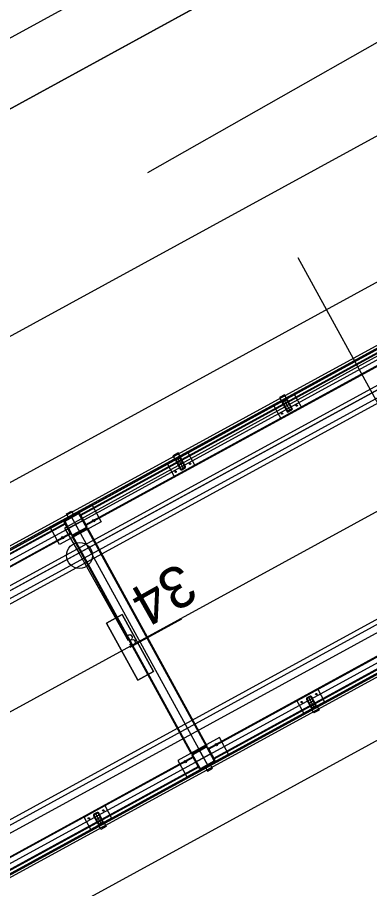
# Model space of a CAD drawing. Extents: x -783978 to -783565, y -1064821 to -1064596.
# Drawn here: x -783750.16 to -783747.19, y -1064675.51 to -1064668.14 of the extents above; entities that cross this region are included whole.
import ezdxf

# ---------------------------------------------------------------- set-up
doc = ezdxf.new("R2010")
doc.units = 0
for name, color, linetype in [('Default', 7, 'Continuous'), ('PS 01_01_10', 7, 'Continuous'), ('PS 01_02_501', 7, 'Continuous'), ('PS 01_02_502', 7, 'Continuous'), ('SO 01_11_01', 7, 'Continuous'), ('SO 01_20_01', 7, 'Continuous'), ('SO 01_50_01', 7, 'Continuous'), ('SO 01_74_01', 7, 'Continuous'), ('SO 01_86_03', 7, 'Continuous'), ('SO 01_86_04', 7, 'Continuous')]:
    doc.layers.add(name, color=color, linetype=linetype)

# ---------------------------------------------------------------- blocks, each defined once
blk = doc.blocks.new('POINT_DISPLAY')
at = {"layer": 'Default'}
blk.add_line((0, 0), (0, 0), dxfattribs=at)

msp = doc.modelspace()

# ---------------------------------------------------------------- linework, layer by layer
at = {"layer": 'PS 01_01_10'}
msp.add_lwpolyline([(-783718.9415, -1064658.9356), (-783725.9639, -1064662.6889), (-783732.3538, -1064665.9121), (-783735.2095, -1064660.6967), (-783789.362, -1064690.3481), (-783783.8255, -1064700.4409), (-783871.4362, -1064748.4249), (-783875.857, -1064749.8347)], dxfattribs=at)
at = {"layer": 'PS 01_02_501'}
msp.add_lwpolyline([(-783952.3105, -1064789.972), (-783925.027, -1064771.233), (-783922.857, -1064767.935), (-783921.1315, -1064767.225), (-783922.344, -1064769.056), (-783920.816, -1064771.043), (-783917.67, -1064770.417), (-783911.05, -1064766.471), (-783887.429, -1064753.525), (-783871.4362, -1064748.4249), (-783783.8277, -1064700.4386), (-783789.362, -1064690.3481), (-783735.2263, -1064660.7067), (-783727.1901, -1064659.072), (-783724.297, -1064658.4835), (-783715.521, -1064653.988), (-783697.391, -1064644.148), (-783676.268, -1064633.506), (-783655.138, -1064621.894)], dxfattribs=at)
at = {"layer": 'PS 01_02_502'}
msp.add_lwpolyline([(-783952.3105, -1064789.972), (-783925.027, -1064771.233), (-783922.857, -1064767.935), (-783921.1315, -1064767.225), (-783922.344, -1064769.056), (-783920.816, -1064771.043), (-783917.67, -1064770.417), (-783911.05, -1064766.471), (-783887.429, -1064753.525), (-783871.4362, -1064748.4249), (-783783.8277, -1064700.4386), (-783789.362, -1064690.3481), (-783735.2263, -1064660.7067), (-783727.1901, -1064659.072), (-783724.297, -1064658.4835), (-783715.521, -1064653.988), (-783697.391, -1064644.148), (-783676.268, -1064633.506), (-783655.138, -1064621.894)], dxfattribs=at)
at = {"layer": 'SO 01_11_01'}
for p, q in [((-783772.8819, -1064683.2217), (-783730.898, -1064660.279)), ((-783749.059, -1064669.4549), (-783743.8421, -1064666.4911))]:
    msp.add_line(p, q, dxfattribs=at)
at = {"layer": 'SO 01_20_01'}
for p, q in [((-783735.0054, -1064663.7532), (-783787.4671, -1064692.4555)), ((-783735.2041, -1064664.4318), (-783786.7885, -1064692.6541)), ((-783786.6445, -1064692.9173), (-783735.3233, -1064664.839)), ((-783738.0171, -1064666.3812), (-783786.4402, -1064692.874)), ((-783786.421, -1064692.9091), (-783737.9979, -1064666.4163)), ((-783737.8741, -1064667.2605), (-783785.3352, -1064693.2269)), ((-783785.6531, -1064694.3127), (-783737.23, -1064667.82)), ((-783737.2108, -1064667.855), (-783785.6339, -1064694.3478)), ((-783737.0912, -1064667.858), (-783785.7805, -1064694.4964)), ((-783785.6366, -1064694.7596), (-783736.9472, -1064668.1212)), ((-783746.2961, -1064673.8055), (-783785.8354, -1064695.4379))]:
    msp.add_line(p, q, dxfattribs=at)
at = {"layer": 'SO 01_50_01'}
for p, q in [((-783786.7885, -1064692.6541), (-783725.4827, -1064659.1131)), ((-783753.521, -1064670.1216), (-783749.1346, -1064667.7218)), ((-783753.521, -1064670.1216), (-783749.1346, -1064667.7218)), ((-783753.521, -1064670.1216), (-783749.1346, -1064667.7218)), ((-783753.521, -1064670.1216), (-783749.1346, -1064667.7218)), ((-783747.3107, -1064671.0555), (-783742.9243, -1064668.6556)), ((-783747.3106, -1064671.0555), (-783742.9242, -1064668.6557)), ((-783747.3106, -1064671.0555), (-783742.9242, -1064668.6557)), ((-783746.8307, -1064671.9327), (-783747.7907, -1064670.1782)), ((-783751.6971, -1064673.4553), (-783747.3107, -1064671.0555)), ((-783751.6971, -1064673.4554), (-783747.3106, -1064671.0555)), ((-783751.6971, -1064673.4554), (-783747.3106, -1064671.0555))]:
    msp.add_line(p, q, dxfattribs=at)
at = {"layer": 'SO 01_74_01'}
for p, q in [((-783735.2185, -1064664.4055), (-783786.6099, -1064692.5222)), ((-783786.6003, -1064692.5398), (-783735.2089, -1064664.423)), ((-783747.0618, -1064670.9478), (-783749.6278, -1064672.3517)), ((-783747.0587, -1064670.9533), (-783749.6248, -1064672.3572)), ((-783749.5828, -1064672.4339), (-783747.0168, -1064671.03)), ((-783749.5798, -1064672.4394), (-783747.0138, -1064671.0355)), ((-783747.9044, -1064671.3347), (-783747.9483, -1064671.3587)), ((-783747.9483, -1064671.3587), (-783747.9291, -1064671.3938)), ((-783747.8996, -1064671.3435), (-783747.9435, -1064671.3675)), ((-783747.9435, -1064671.3675), (-783747.9339, -1064671.385)), ((-783747.9339, -1064671.385), (-783747.89, -1064671.361)), ((-783747.9291, -1064671.3938), (-783747.8852, -1064671.3698)), ((-783747.8852, -1064671.3698), (-783747.9044, -1064671.3347)), ((-783747.89, -1064671.361), (-783747.8996, -1064671.3435)), ((-783748.8037, -1064671.8267), (-783748.8475, -1064671.8507)), ((-783748.7845, -1064671.8618), (-783748.8037, -1064671.8267)), ((-783748.8475, -1064671.8507), (-783748.8283, -1064671.8858)), ((-783748.7989, -1064671.8355), (-783748.8427, -1064671.8594)), ((-783748.8427, -1064671.8594), (-783748.8331, -1064671.877)), ((-783748.8331, -1064671.877), (-783748.7893, -1064671.853)), ((-783748.8283, -1064671.8858), (-783748.7845, -1064671.8618)), ((-783748.7893, -1064671.853), (-783748.7989, -1064671.8355)), ((-783749.7467, -1064672.3426), (-783749.7029, -1064672.3186)), ((-783749.7275, -1064672.3777), (-783749.7467, -1064672.3426)), ((-783749.7029, -1064672.3186), (-783749.6837, -1064672.3537)), ((-783749.6837, -1064672.3537), (-783749.7275, -1064672.3777)), ((-783749.6278, -1064672.3517), (-783749.5798, -1064672.4394)), ((-783749.6248, -1064672.3572), (-783749.5828, -1064672.4339)), ((-783749.7594, -1064672.4237), (-783752.3255, -1064673.8276)), ((-783749.7564, -1064672.4292), (-783752.3224, -1064673.8331)), ((-783749.7114, -1064672.5114), (-783749.7594, -1064672.4237)), ((-783749.7144, -1064672.5059), (-783749.7564, -1064672.4292)), ((-783749.6994, -1064672.5333), (-783749.5678, -1064672.4613)), ((-783749.6924, -1064672.5295), (-783749.5748, -1064672.4652)), ((-783749.5748, -1064672.4652), (-783748.5669, -1064674.3075)), ((-783749.5678, -1064672.4613), (-783748.5599, -1064674.3036)), ((-783752.2805, -1064673.9098), (-783749.7144, -1064672.5059)), ((-783752.2775, -1064673.9153), (-783749.7114, -1064672.5114)), ((-783748.6915, -1064674.3756), (-783749.6994, -1064672.5333)), ((-783748.6845, -1064674.3718), (-783749.6924, -1064672.5295)), ((-783745.9818, -1064672.9216), (-783748.5479, -1064674.3256)), ((-783745.9788, -1064672.9272), (-783748.5449, -1064674.3311)), ((-783785.4388, -1064694.6628), (-783745.8293, -1064672.9921)), ((-783745.8197, -1064673.0096), (-783785.4292, -1064694.6803)), ((-783748.5029, -1064674.4078), (-783745.9368, -1064673.0038)), ((-783748.4999, -1064674.4133), (-783745.9338, -1064673.0094)), ((-783747.6764, -1064673.9913), (-783747.6325, -1064673.9673)), ((-783747.6325, -1064673.9673), (-783747.6133, -1064674.0023)), ((-783747.6572, -1064674.0263), (-783747.6764, -1064673.9913)), ((-783747.6716, -1064674), (-783747.6277, -1064673.976)), ((-783747.662, -1064674.0176), (-783747.6716, -1064674)), ((-783747.6181, -1064673.9936), (-783747.662, -1064674.0176)), ((-783747.6133, -1064674.0023), (-783747.6572, -1064674.0263)), ((-783747.6277, -1064673.976), (-783747.6181, -1064673.9936)), ((-783748.5599, -1064674.3036), (-783748.6915, -1064674.3756)), ((-783748.5669, -1064674.3075), (-783748.6845, -1064674.3718)), ((-783748.5479, -1064674.3256), (-783748.4999, -1064674.4133)), ((-783748.5449, -1064674.3311), (-783748.5029, -1064674.4078)), ((-783748.6795, -1064674.3976), (-783751.2455, -1064675.8015)), ((-783748.6764, -1064674.4031), (-783751.2425, -1064675.807)), ((-783748.6315, -1064674.4853), (-783748.6795, -1064674.3976)), ((-783748.6345, -1064674.4798), (-783748.6764, -1064674.4031)), ((-783751.2006, -1064675.8837), (-783748.6345, -1064674.4798)), ((-783751.1975, -1064675.8892), (-783748.6315, -1064674.4853)), ((-783748.5317, -1064674.4592), (-783748.5756, -1064674.4832)), ((-783748.5756, -1064674.4832), (-783748.5564, -1064674.5183)), ((-783748.5125, -1064674.4943), (-783748.5317, -1064674.4592)), ((-783748.5564, -1064674.5183), (-783748.5125, -1064674.4943)), ((-783749.4748, -1064674.9752), (-783749.431, -1064674.9512)), ((-783749.4556, -1064675.0103), (-783749.4748, -1064674.9752)), ((-783749.47, -1064674.984), (-783749.4262, -1064674.96)), ((-783749.4604, -1064675.0015), (-783749.47, -1064674.984)), ((-783749.4166, -1064674.9775), (-783749.4604, -1064675.0015)), ((-783749.4118, -1064674.9863), (-783749.4556, -1064675.0103)), ((-783749.431, -1064674.9512), (-783749.4118, -1064674.9863)), ((-783749.4262, -1064674.96), (-783749.4166, -1064674.9775))]:
    msp.add_line(p, q, dxfattribs=at)
for points in [[(-783735.1681, -1064664.4976), (-783787.4762, -1064693.1159)], [(-783734.0882, -1064666.4715), (-783786.3963, -1064695.0898)], [(-783747.8935, -1064671.3743), (-783747.9208, -1064671.3893)], [(-783747.8905, -1064671.3799), (-783747.9178, -1064671.3948)], [(-783747.9072, -1064671.3818), (-783747.8592, -1064671.4695)], [(-783747.8473, -1064671.4523), (-783747.8862, -1064671.3811)], [(-783747.8418, -1064671.4492), (-783747.8807, -1064671.3781)], [(-783747.9246, -1064671.4021), (-783747.8856, -1064671.4732)], [(-783747.919, -1064671.3991), (-783747.8801, -1064671.4702)], [(-783747.8612, -1064671.4137), (-783747.9051, -1064671.4377)], [(-783747.8758, -1064671.4715), (-783747.8486, -1064671.4565)], [(-783747.8728, -1064671.477), (-783747.8455, -1064671.4621)], [(-783748.8238, -1064671.8941), (-783748.7849, -1064671.9652)], [(-783748.7928, -1064671.8663), (-783748.82, -1064671.8812)], [(-783748.8183, -1064671.891), (-783748.7793, -1064671.9622)], [(-783748.7897, -1064671.8718), (-783748.817, -1064671.8868)], [(-783748.8064, -1064671.8738), (-783748.7584, -1064671.9615)], [(-783748.7605, -1064671.9056), (-783748.8043, -1064671.9296)], [(-783748.7465, -1064671.9442), (-783748.7855, -1064671.8731)], [(-783748.741, -1064671.9412), (-783748.7799, -1064671.8701)], [(-783748.7751, -1064671.9634), (-783748.7478, -1064671.9485)], [(-783748.772, -1064671.969), (-783748.7448, -1064671.954)], [(-783749.7609, -1064672.396), (-783749.6503, -1064672.3355)], [(-783749.757, -1064672.403), (-783749.6465, -1064672.3425)], [(-783749.6411, -1064672.3441), (-783749.5806, -1064672.4546)], [(-783749.6341, -1064672.3403), (-783749.5736, -1064672.4508)], [(-783749.7052, -1064672.5228), (-783749.7656, -1064672.4123)], [(-783749.6982, -1064672.519), (-783749.7586, -1064672.4084)], [(-783749.6038, -1064672.3955), (-783749.7354, -1064672.4675)], [(-783749.7056, -1064672.3657), (-783748.5537, -1064674.4712)], [(-783749.7056, -1064672.3657), (-783749.6336, -1064672.4973)], [(-783749.5822, -1064672.4601), (-783749.6927, -1064672.5206)], [(-783749.5783, -1064672.4671), (-783749.6889, -1064672.5276)], [(-783747.6888, -1064673.8841), (-783747.7161, -1064673.899)], [(-783747.6858, -1064673.8896), (-783747.7131, -1064673.9045)], [(-783747.7025, -1064673.8915), (-783747.6545, -1064673.9793)], [(-783747.6426, -1064673.962), (-783747.6815, -1064673.8908)], [(-783747.6371, -1064673.959), (-783747.676, -1064673.8878)], [(-783747.7199, -1064673.9118), (-783747.6809, -1064673.983)], [(-783747.7143, -1064673.9088), (-783747.6754, -1064673.9799)], [(-783747.6565, -1064673.9234), (-783747.7004, -1064673.9474)], [(-783747.6711, -1064673.9812), (-783747.6438, -1064673.9663)], [(-783747.6681, -1064673.9867), (-783747.6408, -1064673.9718)], [(-783748.6809, -1064674.3699), (-783748.5704, -1064674.3094)], [(-783748.6771, -1064674.3769), (-783748.5666, -1064674.3164)], [(-783748.5611, -1064674.318), (-783748.5007, -1064674.4285)], [(-783748.5541, -1064674.3142), (-783748.4936, -1064674.4247)], [(-783748.6252, -1064674.4967), (-783748.6857, -1064674.3862)], [(-783748.6182, -1064674.4929), (-783748.6787, -1064674.3823)], [(-783748.5239, -1064674.3694), (-783748.6555, -1064674.4414)], [(-783748.6257, -1064674.3396), (-783748.5537, -1064674.4712)], [(-783748.5022, -1064674.434), (-783748.6128, -1064674.4944)], [(-783748.4984, -1064674.441), (-783748.6089, -1064674.5015)], [(-783749.5183, -1064674.8958), (-783749.4794, -1064674.9669)], [(-783749.4873, -1064674.868), (-783749.5145, -1064674.8829)], [(-783749.5128, -1064674.8927), (-783749.4738, -1064674.9639)], [(-783749.4842, -1064674.8735), (-783749.5115, -1064674.8885)], [(-783749.5009, -1064674.8755), (-783749.4529, -1064674.9632)], [(-783749.455, -1064674.9073), (-783749.4988, -1064674.9313)], [(-783749.441, -1064674.9459), (-783749.48, -1064674.8748)], [(-783749.4355, -1064674.9429), (-783749.4744, -1064674.8718)], [(-783749.4696, -1064674.9651), (-783749.4423, -1064674.9502)], [(-783749.4665, -1064674.9707), (-783749.4393, -1064674.9557)]]:
    msp.add_lwpolyline(points, dxfattribs=at)
for points in [[(-783747.8194, -1064671.3338), (-783747.9949, -1064671.4298), (-783747.9373, -1064671.5351), (-783747.7619, -1064671.4391)], [(-783747.8852, -1064671.3698), (-783747.9291, -1064671.3938), (-783747.8811, -1064671.4815), (-783747.8372, -1064671.4575)], [(-783748.7187, -1064671.8258), (-783748.8941, -1064671.9218), (-783748.8365, -1064672.027), (-783748.6611, -1064671.931)], [(-783749.4534, -1064672.4101), (-783749.8043, -1064672.6021), (-783749.8811, -1064672.4617), (-783749.5302, -1064672.2697)], [(-783747.5667, -1064673.9313), (-783747.7422, -1064674.0272), (-783747.7998, -1064673.922), (-783747.6243, -1064673.826)], [(-783748.455, -1064674.2349), (-783748.8059, -1064674.4268), (-783748.7291, -1064674.5672), (-783748.3782, -1064674.3752)], [(-783749.3652, -1064674.9152), (-783749.5406, -1064675.0112), (-783749.5982, -1064674.9059), (-783749.4228, -1064674.8099)]]:
    msp.add_lwpolyline(points, close=True, dxfattribs=at)
for centre, radius in [((-783747.8026, -1064671.4272), 0.006), ((-783747.9254, -1064671.4944), 0.006), ((-783748.8246, -1064671.9863), 0.006), ((-783748.7018, -1064671.9191), 0.006), ((-783749.5164, -1064672.399), 0.01), ((-783749.7796, -1064672.543), 0.01), ((-783747.6362, -1064673.8667), 0.006), ((-783747.7591, -1064673.9339), 0.006), ((-783748.4797, -1064674.294), 0.01), ((-783748.7429, -1064674.4379), 0.01), ((-783749.4347, -1064674.8506), 0.006), ((-783749.5575, -1064674.9178), 0.006)]:
    msp.add_circle(centre, radius, dxfattribs=at)
for centre, radius, start, end in [((-783747.9163, -1064671.3976), 0.00945, 118.68349, 208.68349), ((-783747.889, -1064671.3826), 0.00945, 28.68349, 118.68349), ((-783747.889, -1064671.3826), 0.00315, 28.68349, 118.68349), ((-783747.9163, -1064671.3976), 0.00315, 118.68349, 208.68349), ((-783747.8501, -1064671.4538), 0.00315, 298.68349, 28.68349), ((-783747.8501, -1064671.4538), 0.00945, 298.68349, 28.68349), ((-783747.8774, -1064671.4687), 0.00945, 208.68349, 298.68349), ((-783747.8774, -1064671.4687), 0.00315, 208.68349, 298.68349), ((-783748.8155, -1064671.8895), 0.00945, 118.68349, 208.68349), ((-783748.8155, -1064671.8895), 0.00315, 118.68349, 208.68349), ((-783748.7882, -1064671.8746), 0.00945, 28.68349, 118.68349), ((-783748.7882, -1064671.8746), 0.00315, 28.68349, 118.68349), ((-783748.7766, -1064671.9607), 0.00945, 208.68349, 298.68349), ((-783748.7766, -1064671.9607), 0.00315, 208.68349, 298.68349), ((-783748.7493, -1064671.9457), 0.00315, 298.68349, 28.68349), ((-783748.7493, -1064671.9457), 0.00945, 298.68349, 28.68349), ((-783749.6446, -1064672.346), 0.012, 28.68349, 118.68349), ((-783749.6446, -1064672.346), 0.004, 28.68349, 118.68349), ((-783749.7551, -1064672.4065), 0.012, 118.68349, 208.68349), ((-783749.7551, -1064672.4065), 0.004, 118.68349, 208.68349), ((-783749.5841, -1064672.4566), 0.004, 298.68349, 28.68349), ((-783749.5841, -1064672.4566), 0.012, 298.68349, 28.68349), ((-783749.6946, -1064672.517), 0.012, 208.68349, 298.68349), ((-783749.6946, -1064672.517), 0.004, 208.68349, 298.68349), ((-783747.6843, -1064673.8923), 0.00945, 28.68349, 118.68349), ((-783747.6843, -1064673.8923), 0.00315, 28.68349, 118.68349), ((-783747.7116, -1064673.9073), 0.00945, 118.68349, 208.68349), ((-783747.7116, -1064673.9073), 0.00315, 118.68349, 208.68349), ((-783747.6454, -1064673.9635), 0.00315, 298.68349, 28.68349), ((-783747.6454, -1064673.9635), 0.00945, 298.68349, 28.68349), ((-783747.6726, -1064673.9784), 0.00945, 208.68349, 298.68349), ((-783747.6726, -1064673.9784), 0.00315, 208.68349, 298.68349), ((-783748.5646, -1064674.3199), 0.012, 28.68349, 118.68349), ((-783748.5646, -1064674.3199), 0.004, 28.68349, 118.68349), ((-783748.6752, -1064674.3804), 0.012, 118.68349, 208.68349), ((-783748.6752, -1064674.3804), 0.004, 118.68349, 208.68349), ((-783748.5042, -1064674.4305), 0.004, 298.68349, 28.68349), ((-783748.5042, -1064674.4305), 0.012, 298.68349, 28.68349), ((-783748.6147, -1064674.4909), 0.012, 208.68349, 298.68349), ((-783748.6147, -1064674.4909), 0.004, 208.68349, 298.68349), ((-783749.51, -1064674.8912), 0.00945, 118.68349, 208.68349), ((-783749.51, -1064674.8912), 0.00315, 118.68349, 208.68349), ((-783749.4827, -1064674.8763), 0.00945, 28.68349, 118.68349), ((-783749.4827, -1064674.8763), 0.00315, 28.68349, 118.68349), ((-783749.4711, -1064674.9624), 0.00945, 208.68349, 298.68349), ((-783749.4711, -1064674.9624), 0.00315, 208.68349, 298.68349), ((-783749.4438, -1064674.9474), 0.00315, 298.68349, 28.68349), ((-783749.4438, -1064674.9474), 0.00945, 298.68349, 28.68349)]:
    msp.add_arc(centre, radius, start, end, dxfattribs=at)
at = {"layer": 'SO 01_86_03'}
for points in [[(-783722.5212, -1064661.7932), (-783724.8208, -1064663.0486), (-783735.2095, -1064660.6967), (-783787.333, -1064689.2371), (-783786.8168, -1064690.1799), (-783783.3595, -1064696.8031), (-783781.9388, -1064699.4088), (-783783.8277, -1064700.4386), (-783871.4362, -1064748.4249), (-783875.857, -1064749.8347), (-783877.5381, -1064747.3925), (-783875.857, -1064749.8347), (-783887.429, -1064753.525), (-783911.05, -1064766.471), (-783917.67, -1064770.417), (-783920.816, -1064771.043), (-783922.344, -1064769.056), (-783922.498, -1064767.051)], [(-783747.0305, -1064676.621), (-783747.6236, -1064677.108), (-783750.7299, -1064678.7824), (-783751.6662, -1064678.8522), (-783782.6812, -1064695.8307), (-783782.8877, -1064696.6917), (-783783.0615, -1064696.8198), (-783783.3595, -1064696.8031), (-783786.8168, -1064690.1799), (-783787.333, -1064689.2371), (-783735.2095, -1064660.6967), (-783724.8208, -1064663.0486), (-783722.5212, -1064661.7932)]]:
    msp.add_lwpolyline(points, dxfattribs=at)
at = {"layer": 'SO 01_86_04'}
for p, q in [((-783749.643, -1064672.6735), (-783749.2252, -1064673.4133)), ((-783749.276, -1064673.1937), (-783749.4076, -1064673.2657)), ((-783749.276, -1064673.1937), (-783749.4076, -1064673.2657)), ((-783749.4076, -1064673.2657), (-783749.276, -1064673.1937)), ((-783749.4076, -1064673.2657), (-783749.276, -1064673.1937)), ((-783749.012, -1064673.6762), (-783749.276, -1064673.1937)), ((-783749.012, -1064673.6762), (-783749.276, -1064673.1937)), ((-783749.276, -1064673.1937), (-783749.012, -1064673.6762)), ((-783749.276, -1064673.1937), (-783749.012, -1064673.6762)), ((-783749.2098, -1064673.471), (-783748.7711, -1064673.231)), ((-783749.4076, -1064673.2657), (-783749.1436, -1064673.7482)), ((-783749.4076, -1064673.2657), (-783749.1436, -1064673.7482)), ((-783749.1436, -1064673.7482), (-783749.4076, -1064673.2657)), ((-783749.1436, -1064673.7482), (-783749.4076, -1064673.2657)), ((-783749.1436, -1064673.7482), (-783749.012, -1064673.6762)), ((-783749.1436, -1064673.7482), (-783749.012, -1064673.6762)), ((-783749.012, -1064673.6762), (-783749.1436, -1064673.7482)), ((-783749.012, -1064673.6762), (-783749.1436, -1064673.7482))]:
    msp.add_line(p, q, dxfattribs=at)
for points in [[(-783735.4626, -1064664.5844), (-783749.7616, -1064672.4637), (-783749.643, -1064672.6735)], [(-783738.3222, -1064666.4797), (-783740.5325, -1064667.689), (-783743.1715, -1064669.1328), (-783745.7538, -1064670.5456), (-783748.4385, -1064672.0145), (-783751.0413, -1064673.4385), (-783753.6847, -1064674.8847), (-783756.3281, -1064676.3309), (-783758.9715, -1064677.7772), (-783761.6149, -1064679.2234), (-783764.2583, -1064680.6696), (-783766.9018, -1064682.1159), (-783769.4633, -1064683.5173), (-783772.109, -1064684.9648), (-783774.7882, -1064686.4306), (-783778.1382, -1064688.2722), (-783783.8139, -1064691.3971), (-783785.747, -1064692.4898)], [(-783747.063, -1064670.9765), (-783746.9575, -1064671.1681), (-783786.6893, -1064692.8619), (-783786.185, -1064693.7636)]]:
    msp.add_lwpolyline(points, dxfattribs=at)
msp.add_circle((-783749.6368, -1064672.6945), 0.1097, dxfattribs=at)

# ---------------------------------------------------------------- block references
at = {"layer": 'SO 01_86_04', "xscale": 0.010000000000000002, "yscale": 0.009999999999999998, "rotation": 28.683491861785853}
for p in [(-783749.276, -1064673.1937), (-783749.276, -1064673.1937), (-783749.4076, -1064673.2657), (-783749.4076, -1064673.2657), (-783749.1436, -1064673.7482), (-783749.1436, -1064673.7482), (-783749.012, -1064673.6762), (-783749.012, -1064673.6762)]:
    msp.add_blockref('POINT_DISPLAY', p, dxfattribs=at)

# ---------------------------------------------------------------- texts
at = {"layer": 'SO 01_86_04'}
for s, height, rotation, p in [('34', 0.351, 209.46001, (-783748.7833, -1064672.7465)), ('3', 0.1, 28.68349, (-783749.2098, -1064673.471))]:
    msp.add_text(s, height=height, rotation=rotation, dxfattribs=at).set_placement(p)

doc.saveas('drawing.dxf')
